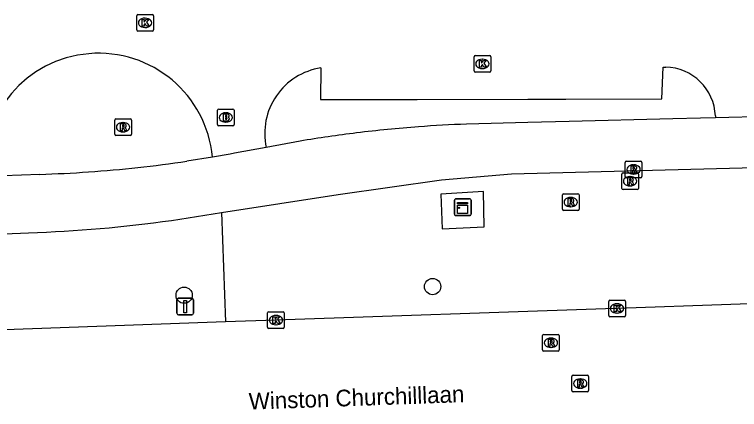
# Model space of a CAD drawing. Extents: x 160891 to 161384, y 386490 to 386907.
# Drawn here: x 161097.43 to 161140.9, y 386495.14 to 386518.85 of the extents above; entities that cross this region are included whole.
import ezdxf

# ---------------------------------------------------------------- set-up
doc = ezdxf.new("R2010")
doc.units = 0
for name, color, linetype in [('IMGEO_Berm_groen', 7, 'Continuous'), ('IMGEO_Boom', 7, 'Continuous'), ('IMGEO_Brandkraan', 7, 'Continuous'), ('IMGEO_Fietspad_gesloten', 7, 'Continuous'), ('IMGEO_Kast', 7, 'Continuous'), ('IMGEO_Kolk', 7, 'Continuous'), ('IMGEO_Openbare_ruimte_label', 7, 'Continuous'), ('IMGEO_Rijbaan_regionaal_gesloten', 7, 'Continuous'), ('IMGEO_Rioolput', 7, 'Continuous'), ('IMGEO_Verkeersbordpaal', 7, 'Continuous'), ('IMGEO_Voetgangersgebied_open', 7, 'Continuous'), ('IMGEO_Voetpad_open', 7, 'Continuous')]:
    doc.layers.add(name, color=color, linetype=linetype)

msp = doc.modelspace()

# ---------------------------------------------------------------- linework, layer by layer
at = {"layer": 'IMGEO_Berm_groen'}
msp.add_lwpolyline([(161109.839, 386506.955), (161110.084, 386500.399)], dxfattribs=at)
at = {"layer": 'IMGEO_Boom'}
for centre in [(161122.501, 386502.519), (161107.601, 386502.002)]:
    msp.add_circle(centre, 0.489, dxfattribs=at)
at = {"layer": 'IMGEO_Brandkraan'}
for p, q in [((161109.599, 386512.245), (161109.599, 386513.097)), ((161109.674, 386513.171), (161110.526, 386513.171)), ((161110.6, 386513.097), (161110.6, 386512.245)), ((161110.087, 386512.951), (161110.112, 386512.951)), ((161110.11, 386512.391), (161110.085, 386512.391)), ((161110.526, 386512.171), (161109.674, 386512.171))]:
    msp.add_line(p, q, dxfattribs=at)
for points in [[(161109.599, 386512.245), (161109.599, 386513.097)], [(161109.674, 386513.171), (161110.526, 386513.171)], [(161110.6, 386513.097), (161110.6, 386512.245)], [(161109.947, 386512.871), (161109.947, 386512.471), (161110.16, 386512.471)], [(161110.178, 386512.871), (161109.947, 386512.871)], [(161110.126, 386512.79), (161110.072, 386512.79), (161110.072, 386512.714)], [(161110.072, 386512.714), (161110.125, 386512.714)], [(161110.134, 386512.638), (161110.072, 386512.638), (161110.072, 386512.557)], [(161110.072, 386512.557), (161110.134, 386512.557)], [(161110.526, 386512.171), (161109.674, 386512.171)]]:
    msp.add_lwpolyline(points, dxfattribs=at)
for centre, radius, start, end in [((161109.676, 386513.095), 0.0765, 91.552, 178.448), ((161109.676, 386513.095), 0.0765, 91.552, 178.448), ((161110.524, 386513.095), 0.0765, 1.552, 88.448), ((161110.524, 386513.095), 0.0765, 1.552, 88.448), ((161110.127, 386512.752), 0.0379, 267.8285, 90.9355), ((161110.182, 386512.726), 0.145, 59.4692, 91.5367), ((161110.207, 386512.773), 0.0922, 285.5137, 58.1501), ((161110.212, 386512.581), 0.105, 301.3115, 78.989), ((161109.676, 386512.247), 0.0765, 181.552, 268.448), ((161109.676, 386512.247), 0.0765, 181.552, 268.448), ((161110.135, 386512.597), 0.0404, 269.8759, 90.5077), ((161110.166, 386512.722), 0.251, 268.6676, 293.5347), ((161110.524, 386512.247), 0.0765, 271.552, 358.448), ((161110.524, 386512.247), 0.0765, 271.552, 358.448)]:
    msp.add_arc(centre, radius, start, end, dxfattribs=at)
for centre, major_axis, ratio, start_param, end_param in [((161110.086, 386512.671), (-0.387, 0.002), 0.722429, 4.712389, 7.853982), ((161110.111, 386512.671), (-0.39, 0.002), 0.717154, 1.570796, 4.712389)]:
    msp.add_ellipse(centre, major_axis=major_axis, ratio=ratio, start_param=start_param, end_param=end_param, dxfattribs=at)
at = {"layer": 'IMGEO_Fietspad_gesloten'}
for points in [[(161142.637, 386512.729), (161139.461, 386512.648)], [(161139.461, 386512.648), (161138.561, 386512.625), (161136.913, 386512.583), (161130.684, 386512.424), (161128.205, 386512.361), (161124.527, 386512.267)], [(161109.839, 386506.955), (161116.836, 386508.035), (161123.035, 386508.931), (161127.225, 386509.29), (161167.964, 386510.348), (161215.734, 386511.569), (161215.758, 386511.159), (161222.805, 386511.284), (161237.753, 386511.488), (161259.697, 386511.429), (161267.164, 386511.376), (161306.097, 386509.668), (161311.73, 386509.285), (161311.776, 386509.705), (161313.071, 386509.592)], [(161114.554, 386511.246), (161112.524, 386510.872)], [(161112.524, 386510.872), (161110.624, 386510.522), (161110.357, 386510.473), (161109.295, 386510.286)], [(161109.295, 386510.286), (161107.767, 386510.044)], [(161098.942, 386509.252), (161095.632, 386509.131)], [(161106.833, 386506.491), (161109.839, 386506.955)], [(161093.386, 386505.539), (161098.265, 386505.752)]]:
    msp.add_lwpolyline(points, dxfattribs=at)
for centre, radius, start, end in [((161127.309, 386436.217), 76.101, 92.09478, 94.25602), ((161127.324, 386435.906), 76.412, 94.24984, 97.05235), ((161127.239, 386436.116), 76.193, 97.00834, 99.58319), ((161096.467, 386586.338), 77.126, 274.01469, 278.42475), ((161096.367, 386588.595), 79.384, 271.85915, 273.97313), ((161095.799, 386584.383), 78.67, 271.79643, 278.06283)]:
    msp.add_arc(centre, radius, start, end, dxfattribs=at)
at = {"layer": 'IMGEO_Kast'}
for p, q in [((161123.804, 386506.855), (161123.804, 386507.696)), ((161123.804, 386507.696), (161123.804, 386506.855)), ((161123.879, 386507.78), (161124.72, 386507.78)), ((161124.72, 386507.78), (161123.879, 386507.78)), ((161124.804, 386507.705), (161124.804, 386506.864)), ((161124.804, 386506.864), (161124.804, 386507.705)), ((161124.729, 386506.78), (161123.888, 386506.78)), ((161123.888, 386506.78), (161124.729, 386506.78))]:
    msp.add_line(p, q, dxfattribs=at)
for points in [[(161123.999, 386507.57), (161124.599, 386507.57), (161124.599, 386507.485), (161123.999, 386507.485), (161123.999, 386507.57)], [(161123.999, 386507.395), (161124.599, 386507.395), (161124.599, 386506.906), (161123.999, 386506.906), (161123.999, 386507.395)]]:
    msp.add_lwpolyline(points, dxfattribs=at)
msp.add_circle((161124.083, 386507.244), 0.0377, dxfattribs=at)
for centre, start, end in [((161123.882, 386507.702), 92.4484, 184.2845), ((161123.882, 386507.702), 92.4484, 184.2845), ((161124.726, 386507.702), 2.4484, 94.2845), ((161124.726, 386507.702), 2.4484, 94.2845), ((161123.882, 386506.858), 182.4484, 274.2845), ((161123.882, 386506.858), 182.4484, 274.2845), ((161124.726, 386506.858), 272.4484, 4.2845), ((161124.726, 386506.858), 272.4484, 4.2845)]:
    msp.add_arc(centre, 0.0779, start, end, dxfattribs=at)
at = {"layer": 'IMGEO_Kolk'}
for p, q in [((161104.756, 386517.922), (161104.756, 386518.774)), ((161104.831, 386518.848), (161105.683, 386518.848)), ((161105.757, 386518.774), (161105.757, 386517.922)), ((161105.244, 386518.628), (161105.269, 386518.628)), ((161105.267, 386518.068), (161105.242, 386518.068)), ((161105.683, 386517.848), (161104.831, 386517.848)), ((161124.985, 386515.46), (161124.985, 386516.312)), ((161125.06, 386516.386), (161125.912, 386516.386)), ((161125.473, 386516.166), (161125.498, 386516.166)), ((161125.986, 386516.312), (161125.986, 386515.46)), ((161125.912, 386515.386), (161125.06, 386515.386)), ((161125.496, 386515.606), (161125.471, 386515.606)), ((161133.062, 386500.778), (161133.062, 386501.63)), ((161133.137, 386501.704), (161133.989, 386501.704)), ((161133.55, 386501.484), (161133.575, 386501.484)), ((161134.063, 386501.63), (161134.063, 386500.778)), ((161112.605, 386500.081), (161112.605, 386500.933)), ((161112.68, 386501.007), (161113.532, 386501.007)), ((161113.606, 386500.933), (161113.606, 386500.081)), ((161133.573, 386500.924), (161133.548, 386500.924)), ((161113.093, 386500.787), (161113.118, 386500.787)), ((161133.989, 386500.704), (161133.137, 386500.704)), ((161113.116, 386500.227), (161113.091, 386500.227)), ((161113.532, 386500.007), (161112.68, 386500.007))]:
    msp.add_line(p, q, dxfattribs=at)
for points in [[(161104.756, 386517.922), (161104.756, 386518.774)], [(161104.831, 386518.848), (161105.683, 386518.848)], [(161105.757, 386518.774), (161105.757, 386517.922)], [(161105.077, 386518.548), (161105.2, 386518.548), (161105.2, 386518.397), (161105.33, 386518.548), (161105.494, 386518.548), (161105.348, 386518.397), (161105.501, 386518.148), (161105.349, 386518.148), (161105.264, 386518.312), (161105.2, 386518.245), (161105.2, 386518.148), (161105.077, 386518.148), (161105.077, 386518.548)], [(161105.683, 386517.848), (161104.831, 386517.848)], [(161124.985, 386515.46), (161124.985, 386516.312)], [(161125.06, 386516.386), (161125.912, 386516.386)], [(161125.986, 386516.312), (161125.986, 386515.46)], [(161125.306, 386516.086), (161125.429, 386516.086), (161125.429, 386515.935), (161125.559, 386516.086), (161125.723, 386516.086), (161125.577, 386515.935), (161125.73, 386515.686), (161125.578, 386515.686), (161125.493, 386515.85), (161125.429, 386515.783), (161125.429, 386515.686), (161125.306, 386515.686), (161125.306, 386516.086)], [(161125.912, 386515.386), (161125.06, 386515.386)], [(161133.062, 386500.778), (161133.062, 386501.63)], [(161133.137, 386501.704), (161133.989, 386501.704)], [(161133.383, 386501.404), (161133.506, 386501.404), (161133.506, 386501.253), (161133.636, 386501.404), (161133.8, 386501.404), (161133.654, 386501.253), (161133.807, 386501.004), (161133.655, 386501.004), (161133.57, 386501.168), (161133.506, 386501.101), (161133.506, 386501.004), (161133.383, 386501.004), (161133.383, 386501.404)], [(161134.063, 386501.63), (161134.063, 386500.778)], [(161112.605, 386500.081), (161112.605, 386500.933)], [(161112.68, 386501.007), (161113.532, 386501.007)], [(161113.606, 386500.933), (161113.606, 386500.081)], [(161112.926, 386500.707), (161113.049, 386500.707), (161113.049, 386500.556), (161113.179, 386500.707), (161113.343, 386500.707), (161113.197, 386500.556), (161113.35, 386500.307), (161113.198, 386500.307), (161113.113, 386500.471), (161113.049, 386500.404), (161113.049, 386500.307), (161112.926, 386500.307), (161112.926, 386500.707)], [(161133.989, 386500.704), (161133.137, 386500.704)], [(161113.532, 386500.007), (161112.68, 386500.007)]]:
    msp.add_lwpolyline(points, dxfattribs=at)
for centre, start, end in [((161104.833, 386518.772), 91.552, 178.448), ((161104.833, 386518.772), 91.552, 178.448), ((161105.681, 386518.772), 1.552, 88.448), ((161105.681, 386518.772), 1.552, 88.448), ((161104.833, 386517.924), 181.552, 268.448), ((161104.833, 386517.924), 181.552, 268.448), ((161105.681, 386517.924), 271.552, 358.448), ((161105.681, 386517.924), 271.552, 358.448), ((161125.062, 386516.31), 91.552, 178.448), ((161125.062, 386516.31), 91.552, 178.448), ((161125.91, 386516.31), 1.552, 88.448), ((161125.91, 386516.31), 1.552, 88.448), ((161125.062, 386515.462), 181.552, 268.448), ((161125.062, 386515.462), 181.552, 268.448), ((161125.91, 386515.462), 271.552, 358.448), ((161125.91, 386515.462), 271.552, 358.448), ((161133.139, 386501.628), 91.552, 178.448), ((161133.139, 386501.628), 91.552, 178.448), ((161133.987, 386501.628), 1.552, 88.448), ((161133.987, 386501.628), 1.552, 88.448), ((161112.682, 386500.931), 91.552, 178.448), ((161112.682, 386500.931), 91.552, 178.448), ((161113.53, 386500.931), 1.552, 88.448), ((161113.53, 386500.931), 1.552, 88.448), ((161133.139, 386500.78), 181.552, 268.448), ((161133.139, 386500.78), 181.552, 268.448), ((161133.987, 386500.78), 271.552, 358.448), ((161133.987, 386500.78), 271.552, 358.448), ((161112.682, 386500.083), 181.552, 268.448), ((161112.682, 386500.083), 181.552, 268.448), ((161113.53, 386500.083), 271.552, 358.448), ((161113.53, 386500.083), 271.552, 358.448)]:
    msp.add_arc(centre, 0.0765, start, end, dxfattribs=at)
for centre, major_axis, ratio, start_param, end_param in [((161105.243, 386518.348), (-0.387, 0.002), 0.722429, 4.712389, 7.853982), ((161105.268, 386518.348), (-0.39, 0.002), 0.717154, 1.570796, 4.712389), ((161125.472, 386515.886), (-0.387, 0.002), 0.722429, 4.712389, 7.853982), ((161125.497, 386515.886), (-0.39, 0.002), 0.717154, 1.570796, 4.712389), ((161133.549, 386501.204), (-0.387, 0.002), 0.722429, 4.712389, 7.853982), ((161133.574, 386501.204), (-0.39, 0.002), 0.717154, 1.570796, 4.712389), ((161113.092, 386500.507), (-0.387, 0.002), 0.722429, 4.712389, 7.853982), ((161113.117, 386500.507), (-0.39, 0.002), 0.717154, 1.570796, 4.712389)]:
    msp.add_ellipse(centre, major_axis=major_axis, ratio=ratio, start_param=start_param, end_param=end_param, dxfattribs=at)
at = {"layer": 'IMGEO_Rijbaan_regionaal_gesloten'}
for points in [[(161323.08, 386507.769), (161322.733, 386507.751), (161292.306, 386506.7), (161273.833, 386506.048), (161254.372, 386505.373), (161233.906, 386504.66), (161214.429, 386503.969), (161194.971, 386503.319), (161175.497, 386502.675), (161154.024, 386501.918), (161133.563, 386501.204), (161132.874, 386501.189), (161113.106, 386500.507), (161110.084, 386500.399)], [(161110.084, 386500.399), (161094.63, 386499.845), (161093.606, 386499.805)]]:
    msp.add_lwpolyline(points, dxfattribs=at)
at = {"layer": 'IMGEO_Rioolput'}
for p, q in [((161103.435, 386511.657), (161103.435, 386512.509)), ((161103.51, 386512.583), (161104.362, 386512.583)), ((161103.923, 386512.363), (161103.948, 386512.363)), ((161104.436, 386512.509), (161104.436, 386511.657)), ((161103.946, 386511.803), (161103.921, 386511.803)), ((161104.362, 386511.583), (161103.51, 386511.583)), ((161134.049, 386509.122), (161134.049, 386509.974)), ((161134.124, 386510.048), (161134.976, 386510.048)), ((161134.537, 386509.828), (161134.562, 386509.828)), ((161135.05, 386509.974), (161135.05, 386509.122)), ((161133.844, 386508.412), (161133.844, 386509.264)), ((161133.919, 386509.338), (161134.771, 386509.338)), ((161134.56, 386509.268), (161134.535, 386509.268)), ((161134.845, 386509.264), (161134.845, 386508.412)), ((161134.976, 386509.048), (161134.124, 386509.048)), ((161134.332, 386509.118), (161134.357, 386509.118)), ((161134.771, 386508.338), (161133.919, 386508.338)), ((161134.355, 386508.558), (161134.33, 386508.558)), ((161130.282, 386507.165), (161130.282, 386508.017)), ((161130.357, 386508.091), (161131.209, 386508.091)), ((161131.283, 386508.017), (161131.283, 386507.165)), ((161130.77, 386507.871), (161130.795, 386507.871)), ((161131.209, 386507.091), (161130.357, 386507.091)), ((161130.793, 386507.311), (161130.768, 386507.311)), ((161129.171, 386499.648), (161130.023, 386499.648)), ((161129.096, 386498.722), (161129.096, 386499.574)), ((161129.584, 386499.428), (161129.609, 386499.428)), ((161130.097, 386499.574), (161130.097, 386498.722)), ((161129.607, 386498.868), (161129.582, 386498.868)), ((161130.023, 386498.648), (161129.171, 386498.648)), ((161130.852, 386496.274), (161130.852, 386497.126)), ((161130.927, 386497.2), (161131.779, 386497.2)), ((161131.853, 386497.126), (161131.853, 386496.274)), ((161131.34, 386496.98), (161131.365, 386496.98)), ((161131.779, 386496.2), (161130.927, 386496.2)), ((161131.363, 386496.42), (161131.338, 386496.42))]:
    msp.add_line(p, q, dxfattribs=at)
for points in [[(161103.435, 386511.657), (161103.435, 386512.509)], [(161103.51, 386512.583), (161104.362, 386512.583)], [(161104.024, 386512.281), (161103.772, 386512.283), (161103.772, 386511.883)], [(161104.436, 386512.509), (161104.436, 386511.657)], [(161103.772, 386511.883), (161103.896, 386511.883), (161103.896, 386512.045), (161103.907, 386512.045)], [(161103.95, 386512.202), (161103.896, 386512.202), (161103.896, 386512.121)], [(161103.896, 386512.121), (161103.948, 386512.121)], [(161103.954, 386512.016), (161104.025, 386511.883), (161104.165, 386511.883), (161104.1, 386512.009)], [(161104.362, 386511.583), (161103.51, 386511.583)], [(161134.049, 386509.122), (161134.049, 386509.974)], [(161134.124, 386510.048), (161134.976, 386510.048)], [(161134.638, 386509.746), (161134.386, 386509.748), (161134.386, 386509.348)], [(161134.564, 386509.667), (161134.51, 386509.667), (161134.51, 386509.586)], [(161135.05, 386509.974), (161135.05, 386509.122)], [(161133.844, 386508.412), (161133.844, 386509.264)], [(161133.919, 386509.338), (161134.771, 386509.338)], [(161134.386, 386509.348), (161134.51, 386509.348), (161134.51, 386509.51), (161134.521, 386509.51)], [(161134.51, 386509.586), (161134.562, 386509.586)], [(161134.568, 386509.481), (161134.639, 386509.348), (161134.779, 386509.348), (161134.714, 386509.474)], [(161134.845, 386509.264), (161134.845, 386508.412)], [(161134.976, 386509.048), (161134.124, 386509.048)], [(161134.433, 386509.036), (161134.181, 386509.038), (161134.181, 386508.638)], [(161134.181, 386508.638), (161134.305, 386508.638), (161134.305, 386508.8), (161134.316, 386508.8)], [(161134.359, 386508.957), (161134.305, 386508.957), (161134.305, 386508.876)], [(161134.305, 386508.876), (161134.357, 386508.876)], [(161134.363, 386508.771), (161134.434, 386508.638), (161134.574, 386508.638), (161134.509, 386508.764)], [(161134.771, 386508.338), (161133.919, 386508.338)], [(161130.282, 386507.165), (161130.282, 386508.017)], [(161130.357, 386508.091), (161131.209, 386508.091)], [(161131.283, 386508.017), (161131.283, 386507.165)], [(161130.871, 386507.789), (161130.619, 386507.791), (161130.619, 386507.391)], [(161130.619, 386507.391), (161130.743, 386507.391), (161130.743, 386507.553), (161130.754, 386507.553)], [(161130.797, 386507.71), (161130.743, 386507.71), (161130.743, 386507.629)], [(161130.743, 386507.629), (161130.795, 386507.629)], [(161130.801, 386507.524), (161130.872, 386507.391), (161131.012, 386507.391), (161130.947, 386507.517)], [(161131.209, 386507.091), (161130.357, 386507.091)], [(161129.171, 386499.648), (161130.023, 386499.648)], [(161129.096, 386498.722), (161129.096, 386499.574)], [(161129.685, 386499.346), (161129.433, 386499.348), (161129.433, 386498.948)], [(161129.611, 386499.267), (161129.557, 386499.267), (161129.557, 386499.186)], [(161129.557, 386499.186), (161129.609, 386499.186)], [(161130.097, 386499.574), (161130.097, 386498.722)], [(161129.433, 386498.948), (161129.557, 386498.948), (161129.557, 386499.11), (161129.568, 386499.11)], [(161129.615, 386499.081), (161129.686, 386498.948), (161129.826, 386498.948), (161129.761, 386499.074)], [(161130.023, 386498.648), (161129.171, 386498.648)], [(161130.852, 386496.274), (161130.852, 386497.126)], [(161130.927, 386497.2), (161131.779, 386497.2)], [(161131.853, 386497.126), (161131.853, 386496.274)], [(161131.441, 386496.898), (161131.189, 386496.9), (161131.189, 386496.5)], [(161131.189, 386496.5), (161131.313, 386496.5), (161131.313, 386496.662), (161131.324, 386496.662)], [(161131.367, 386496.819), (161131.313, 386496.819), (161131.313, 386496.738)], [(161131.313, 386496.738), (161131.365, 386496.738)], [(161131.371, 386496.633), (161131.442, 386496.5), (161131.582, 386496.5), (161131.517, 386496.626)], [(161131.779, 386496.2), (161130.927, 386496.2)]]:
    msp.add_lwpolyline(points, dxfattribs=at)
for centre, radius, start, end in [((161103.512, 386512.507), 0.0765, 91.552, 178.448), ((161103.512, 386512.507), 0.0765, 91.552, 178.448), ((161104.023, 386512.171), 0.109, 350.3612, 89.416), ((161104.36, 386512.507), 0.0765, 1.552, 88.448), ((161104.36, 386512.507), 0.0765, 1.552, 88.448), ((161103.906, 386511.992), 0.0533, 26.0293, 88.6989), ((161103.932, 386512.31), 0.19, 274.7715, 282.9687), ((161103.956, 386512.106), 0.0964, 77.0061, 93.1865), ((161103.97, 386512.163), 0.0378, 276.6634, 79.6772), ((161104.021, 386512.171), 0.112, 277.5842, 350.9817), ((161104.005, 386511.956), 0.108, 29.5134, 73.7905), ((161103.512, 386511.659), 0.0765, 181.552, 268.448), ((161103.512, 386511.659), 0.0765, 181.552, 268.448), ((161104.36, 386511.659), 0.0765, 271.552, 358.448), ((161104.36, 386511.659), 0.0765, 271.552, 358.448), ((161134.126, 386509.972), 0.0765, 91.552, 178.448), ((161134.126, 386509.972), 0.0765, 91.552, 178.448), ((161134.57, 386509.571), 0.0964, 77.0061, 93.1865), ((161134.584, 386509.628), 0.0378, 276.6634, 79.6772), ((161134.637, 386509.636), 0.109, 350.3612, 89.416), ((161134.635, 386509.636), 0.112, 277.5842, 350.9817), ((161134.974, 386509.972), 0.0765, 1.552, 88.448), ((161134.974, 386509.972), 0.0765, 1.552, 88.448), ((161133.921, 386509.262), 0.0765, 91.552, 178.448), ((161133.921, 386509.262), 0.0765, 91.552, 178.448), ((161134.52, 386509.457), 0.0533, 26.0293, 88.6989), ((161134.546, 386509.775), 0.19, 274.7715, 282.9687), ((161134.619, 386509.421), 0.108, 29.5134, 73.7905), ((161134.769, 386509.262), 0.0765, 1.552, 88.448), ((161134.769, 386509.262), 0.0765, 1.552, 88.448), ((161134.126, 386509.124), 0.0765, 181.552, 268.448), ((161134.126, 386509.124), 0.0765, 181.552, 268.448), ((161134.315, 386508.747), 0.0533, 26.0293, 88.6989), ((161134.341, 386509.065), 0.19, 274.7715, 282.9687), ((161134.365, 386508.861), 0.0964, 77.0061, 93.1865), ((161134.379, 386508.918), 0.0378, 276.6634, 79.6772), ((161134.432, 386508.926), 0.109, 350.3612, 89.416), ((161134.43, 386508.926), 0.112, 277.5842, 350.9817), ((161134.414, 386508.711), 0.108, 29.5134, 73.7905), ((161134.974, 386509.124), 0.0765, 271.552, 358.448), ((161134.974, 386509.124), 0.0765, 271.552, 358.448), ((161133.921, 386508.414), 0.0765, 181.552, 268.448), ((161133.921, 386508.414), 0.0765, 181.552, 268.448), ((161134.769, 386508.414), 0.0765, 271.552, 358.448), ((161134.769, 386508.414), 0.0765, 271.552, 358.448), ((161130.359, 386508.015), 0.0765, 91.552, 178.448), ((161130.359, 386508.015), 0.0765, 91.552, 178.448), ((161131.207, 386508.015), 0.0765, 1.552, 88.448), ((161131.207, 386508.015), 0.0765, 1.552, 88.448), ((161130.753, 386507.5), 0.0533, 26.0293, 88.6989), ((161130.779, 386507.818), 0.19, 274.7715, 282.9687), ((161130.803, 386507.614), 0.0964, 77.0061, 93.1865), ((161130.817, 386507.671), 0.0378, 276.6634, 79.6772), ((161130.87, 386507.679), 0.109, 350.3612, 89.416), ((161130.868, 386507.679), 0.112, 277.5842, 350.9817), ((161130.852, 386507.464), 0.108, 29.5134, 73.7905), ((161130.359, 386507.167), 0.0765, 181.552, 268.448), ((161130.359, 386507.167), 0.0765, 181.552, 268.448), ((161131.207, 386507.167), 0.0765, 271.552, 358.448), ((161131.207, 386507.167), 0.0765, 271.552, 358.448), ((161129.173, 386499.572), 0.0765, 91.552, 178.448), ((161129.173, 386499.572), 0.0765, 91.552, 178.448), ((161130.021, 386499.572), 0.0765, 1.552, 88.448), ((161130.021, 386499.572), 0.0765, 1.552, 88.448), ((161129.593, 386499.375), 0.19, 274.7715, 282.9687), ((161129.617, 386499.171), 0.0964, 77.0061, 93.1865), ((161129.631, 386499.228), 0.0378, 276.6634, 79.6772), ((161129.684, 386499.236), 0.109, 350.3612, 89.416), ((161129.682, 386499.236), 0.112, 277.5842, 350.9817), ((161129.567, 386499.057), 0.0533, 26.0293, 88.6989), ((161129.666, 386499.021), 0.108, 29.5134, 73.7905), ((161129.173, 386498.724), 0.0765, 181.552, 268.448), ((161129.173, 386498.724), 0.0765, 181.552, 268.448), ((161130.021, 386498.724), 0.0765, 271.552, 358.448), ((161130.021, 386498.724), 0.0765, 271.552, 358.448), ((161130.929, 386497.124), 0.0765, 91.552, 178.448), ((161130.929, 386497.124), 0.0765, 91.552, 178.448), ((161131.777, 386497.124), 0.0765, 1.552, 88.448), ((161131.777, 386497.124), 0.0765, 1.552, 88.448), ((161131.323, 386496.609), 0.0533, 26.0293, 88.6989), ((161131.349, 386496.927), 0.19, 274.7715, 282.9687), ((161131.373, 386496.723), 0.0964, 77.0061, 93.1865), ((161131.387, 386496.78), 0.0378, 276.6634, 79.6772), ((161131.44, 386496.788), 0.109, 350.3612, 89.416), ((161131.438, 386496.788), 0.112, 277.5842, 350.9817), ((161131.422, 386496.573), 0.108, 29.5134, 73.7905), ((161130.929, 386496.276), 0.0765, 181.552, 268.448), ((161130.929, 386496.276), 0.0765, 181.552, 268.448), ((161131.777, 386496.276), 0.0765, 271.552, 358.448), ((161131.777, 386496.276), 0.0765, 271.552, 358.448)]:
    msp.add_arc(centre, radius, start, end, dxfattribs=at)
for centre, major_axis, ratio, start_param, end_param in [((161103.922, 386512.083), (-0.387, 0.002), 0.722429, 4.712389, 7.853982), ((161103.947, 386512.083), (-0.39, 0.002), 0.717154, 1.570796, 4.712389), ((161134.536, 386509.548), (-0.387, 0.002), 0.722429, 4.712389, 7.853982), ((161134.561, 386509.548), (-0.39, 0.002), 0.717154, 1.570796, 4.712389), ((161134.331, 386508.838), (-0.387, 0.002), 0.722429, 4.712389, 7.853982), ((161134.356, 386508.838), (-0.39, 0.002), 0.717154, 1.570796, 4.712389), ((161130.769, 386507.591), (-0.387, 0.002), 0.722429, 4.712389, 7.853982), ((161130.794, 386507.591), (-0.39, 0.002), 0.717154, 1.570796, 4.712389), ((161129.583, 386499.148), (-0.387, 0.002), 0.722429, 4.712389, 7.853982), ((161129.608, 386499.148), (-0.39, 0.002), 0.717154, 1.570796, 4.712389), ((161131.339, 386496.7), (-0.387, 0.002), 0.722429, 4.712389, 7.853982), ((161131.364, 386496.7), (-0.39, 0.002), 0.717154, 1.570796, 4.712389)]:
    msp.add_ellipse(centre, major_axis=major_axis, ratio=ratio, start_param=start_param, end_param=end_param, dxfattribs=at)
at = {"layer": 'IMGEO_Verkeersbordpaal'}
for p, q in [((161107.263, 386501.813), (161108.053, 386501.813)), ((161108.053, 386501.813), (161107.263, 386501.813)), ((161107.163, 386500.913), (161107.163, 386501.713)), ((161107.163, 386501.713), (161107.163, 386500.913)), ((161108.153, 386501.713), (161108.153, 386500.913)), ((161108.153, 386500.913), (161108.153, 386501.713)), ((161108.053, 386500.813), (161107.263, 386500.813)), ((161107.263, 386500.813), (161108.053, 386500.813))]:
    msp.add_line(p, q, dxfattribs=at)
msp.add_lwpolyline([(161107.583, 386501.688), (161107.733, 386501.688), (161107.733, 386500.938), (161107.583, 386500.938), (161107.583, 386501.688)], dxfattribs=at)
for centre, start, end in [((161107.263, 386501.713), 90, 180), ((161107.263, 386501.713), 90, 180), ((161108.053, 386501.713), 0, 90), ((161108.053, 386501.713), 360, 90), ((161107.263, 386500.913), 180, 270), ((161107.263, 386500.913), 180, 270), ((161108.053, 386500.913), 270, 0), ((161108.053, 386500.913), 270, 0)]:
    msp.add_arc(centre, 0.1, start, end, dxfattribs=at)
at = {"layer": 'IMGEO_Voetgangersgebied_open'}
for points in [[(161115.797, 386515.64), (161115.774, 386513.737), (161117.674, 386513.741), (161121.578, 386513.75), (161128.205, 386513.766), (161130.488, 386513.771), (161136.246, 386513.784), (161136.328, 386515.689), (161136.477, 386515.69)], [(161139.456, 386512.756), (161139.461, 386512.648)]]:
    msp.add_lwpolyline(points, dxfattribs=at)
for centre, radius, start, end in [((161102.467, 386509.665), 6.856, 5.1968, 184.4672), ((161116.404, 386511.716), 3.971, 98.7933, 192.2713), ((161136.411, 386512.644), 3.047, 2.1139, 88.7582)]:
    msp.add_arc(centre, radius, start, end, dxfattribs=at)
at = {"layer": 'IMGEO_Voetpad_open'}
msp.add_lwpolyline([(161123.077, 386505.983), (161125.6, 386506.109), (161125.558, 386508.215), (161123.003, 386508.068), (161123.077, 386505.983)], dxfattribs=at)

# ---------------------------------------------------------------- texts
at = {"layer": 'IMGEO_Openbare_ruimte_label'}
msp.add_text('Winston Churchilllaan', height=1, rotation=2.0065, dxfattribs=at).set_placement((161111.494, 386495.13))

doc.saveas('drawing.dxf')
